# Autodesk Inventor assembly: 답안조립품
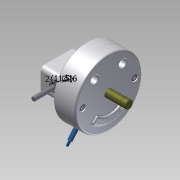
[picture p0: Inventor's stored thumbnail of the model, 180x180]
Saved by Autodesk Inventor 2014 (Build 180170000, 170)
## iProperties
Created: 2015-04
Part Number: 답안조립품
Document SubType Name: Assembly
Designer: Administrator
Mass: 3435.4 g
Surface Area: 3333.71 cm^2
Volume: 1140.85 cm^3
Density: 3.01126 g/cm^3
Author: Administrator
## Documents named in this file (15)
- C:\Documents and Settings\Administrator\바탕 화면\350406V1017\답안조립품.iam
- C:\Documents and Settings\Administrator\바탕 화면\350406V1017\본체.ipt
- C:\Documents and Settings\Administrator\바탕 화면\350406V1017\커버.ipt
- C:\Documents and Settings\Administrator\바탕 화면\350406V1017\커버2.ipt
- C:\Documents and Settings\Administrator\바탕 화면\350406V1017\베어링62_22.ipt
- C:\Documents and Settings\Administrator\바탕 화면\350406V1017\축.ipt
- C:\Documents and Settings\Administrator\바탕 화면\350406V1017\멈춤링.ipt
- C:\Documents and Settings\Administrator\바탕 화면\350406V1017\M 5 x 12.ipt
- C:\Documents and Settings\Administrator\바탕 화면\350406V1017\M 10 x 35.ipt
- C:\Documents and Settings\Administrator\바탕 화면\350406V1017\슬라이더2.ipt
- C:\Documents and Settings\Administrator\바탕 화면\350406V1017\슬라이더.ipt
- C:\Documents and Settings\Administrator\바탕 화면\350406V1017\평행핀.ipt
- C:\Documents and Settings\Administrator\바탕 화면\350406V1017\가변스프링.ipt
- C:\Documents and Settings\Administrator\바탕 화면\350406V1017\부시.ipt
- C:\Documents and Settings\Administrator\바탕 화면\350406V1017\슬라이더3.ipt
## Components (6 placed, 4 different names)
1. M 5 x 12:1
2. M 5 x 12:2
3. M 10 x 35:1
4. M 10 x 35:2
5. KS B 1320 B B 5 x  20:1
6. 가변스프링:1
